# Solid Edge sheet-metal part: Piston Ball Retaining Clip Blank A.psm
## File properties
Title: Piston Ball Retaining Clip
Author: Dan
Template: Normal.psm
Last saved by: Dan
Revision: 34
Application: Solid Edge
Density: 0 kg/dm^3
Accuracy: 0.99
Material Thickness: 1.1 mm
Bend Radius: 3 mm
Relief Width: 3 mm
Relief Length: 3 mm
Neutral Factor: 0.33
Minimum Arc Length: 0.1 mm
Deviational Tolerance: 0.1 mm
Document Number: P52-014
Material: steel
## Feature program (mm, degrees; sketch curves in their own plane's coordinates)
base tab "unnamed BaseTab 1"
sheet metal cutout "unnamed SheetMetalCutout 1"
pattern "unnamed Pattern 1" of "unnamed SheetMetalCutout 1"
pattern "unnamed Pattern 2"
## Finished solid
Body 1: solid body, 14 faces, 36 edges, 24 vertices.
  Faces by surface: plane 8, cylinder 6
  Edges by curve: line 24, circle 12
Bounding box of the edges (mm): 28.497 x 32.660 x 1.100, from (-10.9969, -16.3302, -1.1) to (17.5, 16.3302, 0).
Cylindrical faces by radius (mm): R2.5 x3, R17.5 x3
Planar faces by outward normal: +z 1, -z 1, oblique 6
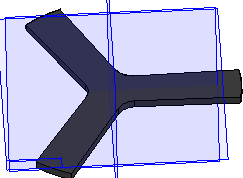
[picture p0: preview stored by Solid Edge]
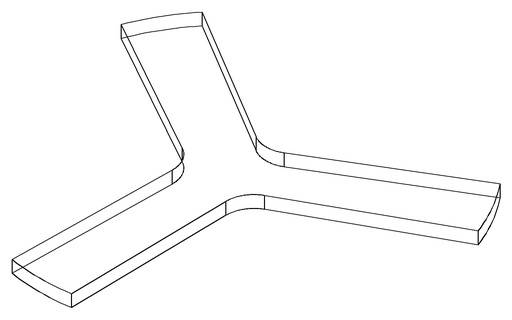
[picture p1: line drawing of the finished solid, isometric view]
